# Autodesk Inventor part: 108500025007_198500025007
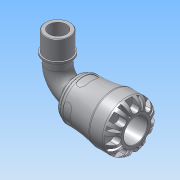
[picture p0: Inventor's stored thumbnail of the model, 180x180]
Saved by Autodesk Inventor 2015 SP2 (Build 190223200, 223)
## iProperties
Created: 2016-12
Part Number: 108500025007_198500025007
Material: PVC-Piping
Description: PLASSON 90° ELBOW WITH THREADED MALE OFFTAKE 25X3/4" SERIES 1
Document SubType Name: Modeling
Designer: KIM
Mass: 664.223 g
Surface Area: 733.008 cm^2
Volume: 474.445 cm^3
Density: 1.4 g/cm^3
Appearance: Smooth - White
Author: KIM
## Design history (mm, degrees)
derived "1085.ipt"
feature "Solid1::1085.ipt"
tag "TaggingFeature1"
body "Solid1"
other parameters: "d1" = 20.16, "d2" = 25, "d3" = 31.25, "d4" = 47, "d8" = 39.95, "d13" = 6.3, "d14" = 6.3, "d15" = 0, "d17" = 360 deg, "d19" = 8 deg, "d20" = 0.5, "d21" = 0.5, "d22" = 8 deg, "d24" = 0, "d26" = 360 deg, "d33" = 4.7, "d43" = 36.66, "d51" = 0.47, "d54" = 8.75, "d55" = 5.5, "d57" = 12.348, "d58" = 0, "d74" = 0, "d78" = 48, "d82" = 0.5, "d115" = 360 deg, "d207" = 90 deg, "d228" = 7.4375, "d247" = 0.94, "d248" = 2.88, "d268" = 21.9725, "d269" = 2.88, "d270" = 74, "d276" = 26.441, "d277" = 17, "d278" = 29.0851, "d279" = 45, "d280" = 18.7, "d281" = 3.96615, "d283" = 23.7969, "d286" = 0, "d287" = 0, "d288" = 18.5087, "d290" = 6.43155, "d292" = 30 deg, "d_" = 25, "E_" = 47, "l_" = 48, "A_" = 74, "A_1" = 45, "l_2" = 17, "R_" = 26.441, "d9" = 7.875, "d11" = 47, "d12" = 31.25, "d289" = 18.5087
